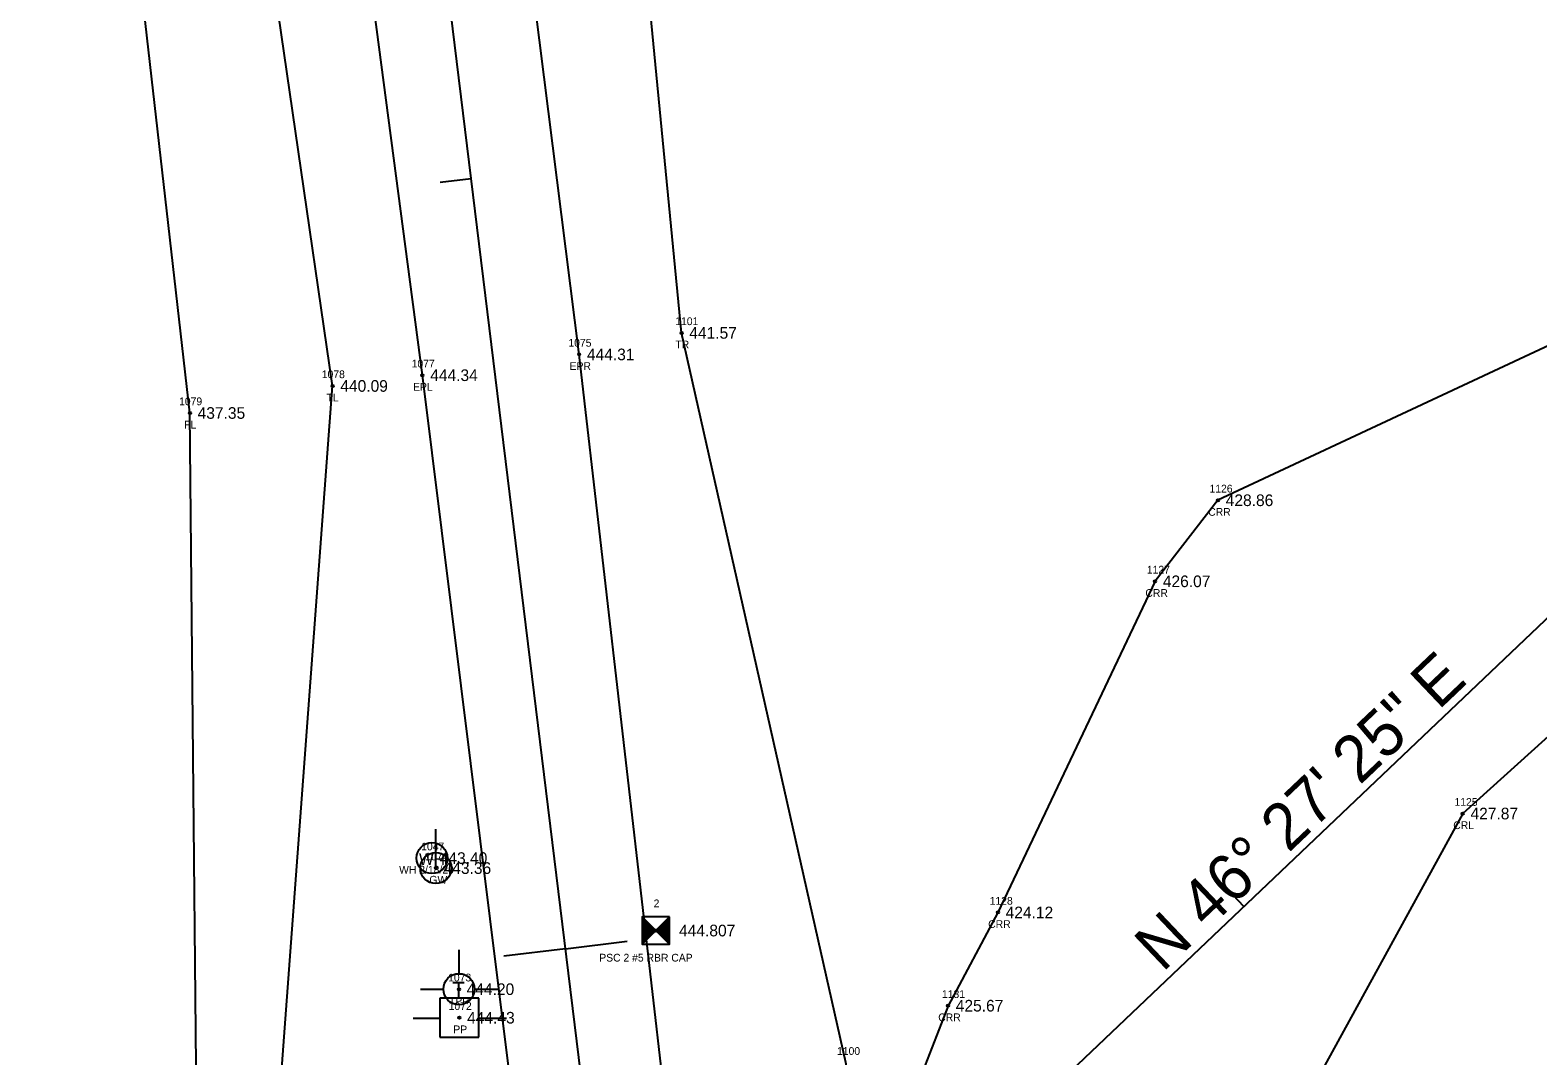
# Model space of a CAD drawing. Extents: x 1858454 to 1858924, y 1147053 to 1148170.
# Drawn here: x 1858606.4 to 1858800.8, y 1147671.2 to 1147803.4 of the extents above; entities that cross this region are included whole.
import ezdxf

# ---------------------------------------------------------------- set-up
doc = ezdxf.new("R2010")
doc.units = 0
for name, color, linetype in [('RD_EX_Fence_Other', 7, 'Continuous'), ('RD_EX_Fence_Other_txCode', 7, 'Continuous'), ('RD_EX_H2O', 7, 'Continuous'), ('RD_EX_H2O_txCode', 7, 'Continuous'), ('RD_EX_Road', 7, 'Continuous'), ('RD_EX_Road_txCode', 7, 'Continuous'), ('RD_EX_TX_Fence_Other_ELEV', 7, 'Continuous'), ('RD_EX_TX_H2O_ELEV', 7, 'Continuous'), ('RD_EX_TX_Road_ELEV', 7, 'Continuous'), ('RD_EX_TX_UT_ELEV', 7, 'Continuous'), ('RD_EX_TX_VEG_ELEV', 7, 'Continuous'), ('RD_EX_UT', 7, 'Continuous'), ('RD_EX_UT_txCode', 7, 'Continuous'), ('RD_EX_VEG', 7, 'Continuous'), ('RD_EX_VEG_txCode', 7, 'Continuous'), ('RD_HC_Cl', 7, 'Continuous'), ('RD_HC_Data', 7, 'Continuous'), ('RD_HC_Data_Tic', 7, 'Continuous'), ('RD_HC_Survey', 7, 'Continuous'), ('RD_HC_Survey_ELEV', 7, 'Continuous'), ('RD_HC_txCode', 7, 'Continuous'), ('RD_SMD_Locator', 7, 'Continuous')]:
    doc.layers.add(name, color=color, linetype=linetype)

msp = doc.modelspace()

# ---------------------------------------------------------------- linework, layer by layer
at = {"layer": 'RD_EX_Fence_Other'}
msp.add_lwpolyline([(1858628.27, 1147625.58), (1858627.01, 1147754.05), (1858615.95, 1147851.08), (1858606.98, 1147957.76), (1858595.17, 1148052.68), (1858581.78, 1148154.12)], dxfattribs=at)
at = {"layer": 'RD_EX_H2O'}
for points in [[(1858879.83, 1148102.54), (1858871.42, 1148034.27), (1858866.93, 1147971.73), (1858863.21, 1147909.44), (1858860.9, 1147860.04), (1858873.82, 1147825.54), (1858891.79, 1147781.55), (1858894.95, 1147773.07), (1858887.01, 1147735.25), (1858825.08, 1147733.03), (1858791.14, 1147702.41), (1858765.02, 1147654.77), (1858740.99, 1147628.76), (1858706.35, 1147596.83), (1858671.87, 1147580.02), (1858637.61, 1147560.56), (1858613.46, 1147539.88), (1858609.2, 1147499), (1858608.26, 1147474.71), (1858583.43, 1147442.99), (1858542.68, 1147417.32), (1858497.34, 1147430.55)], [(1858842, 1147848.22), (1858847.52, 1147794.04), (1858841.16, 1147786.48), (1858816.23, 1147769.28), (1858759.58, 1147742.8), (1858751.47, 1147732.35), (1858731.2, 1147689.66), (1858724.77, 1147677.64), (1858718.76, 1147662.14), (1858713.87, 1147646.5), (1858696.23, 1147629.99), (1858681.73, 1147631.9), (1858663.61, 1147613.98), (1858627.73, 1147602.37), (1858587.46, 1147561.81), (1858570.79, 1147529.07), (1858577.35, 1147512.16), (1858564.18, 1147528.65), (1858536.5, 1147564.8), (1858503.8, 1147609.24)]]:
    msp.add_lwpolyline(points, dxfattribs=at)
for radius in [2, 0.005]:
    msp.add_circle((1858658.23, 1147696.67), radius, dxfattribs=at)
at = {"layer": 'RD_EX_Road'}
for points in [[(1858679.02, 1147660.19), (1858688.73, 1147661.54), (1858677.21, 1147761.6), (1858664.75, 1147860.38), (1858652.33, 1147959.9), (1858640.18, 1148058.71), (1858627.63, 1148158.94)], [(1858679.02, 1147660.19), (1858669.49, 1147658.82), (1858657, 1147758.92), (1858643.96, 1147857.84), (1858631.87, 1147958), (1858619.69, 1148055.49), (1858606.59, 1148156.75)]]:
    msp.add_lwpolyline(points, dxfattribs=at)
at = {"layer": 'RD_EX_UT'}
for p, q in [((1858658.73, 1147695.38), (1858658.73, 1147700.38)), ((1858661.7, 1147684.84), (1858661.7, 1147681.77)), ((1858656.76, 1147679.78), (1858659.7, 1147679.78)), ((1858664.25, 1147678.6), (1858659.25, 1147678.6)), ((1858659.25, 1147678.6), (1858659.25, 1147673.6)), ((1858663.7, 1147679.78), (1858666.76, 1147679.78)), ((1858664.25, 1147673.6), (1858664.25, 1147678.6)), ((1858655.82, 1147676.04), (1858659.29, 1147676.04)), ((1858664.18, 1147676.04), (1858667.82, 1147676.04)), ((1858659.25, 1147673.6), (1858664.25, 1147673.6))]:
    msp.add_line(p, q, dxfattribs=at)
for centre in [(1858658.73, 1147695.38), (1858661.7, 1147679.77)]:
    msp.add_circle(centre, 2, dxfattribs=at)
at = {"layer": 'RD_EX_VEG'}
for points in [[(1858786.58, 1147073.62), (1858775.98, 1147174.64), (1858762.89, 1147274.03), (1858752.24, 1147373.24), (1858736.96, 1147479.89), (1858729.06, 1147571.9), (1858711.6, 1147670.3), (1858690.41, 1147764.38), (1858680.89, 1147862.43), (1858668.42, 1147961.01), (1858651.26, 1148061.01), (1858641.53, 1148160.37)], [(1858726.29, 1147071.02), (1858708.41, 1147166.41), (1858698.92, 1147264.27), (1858694.52, 1147368.74), (1858682.22, 1147467.57), (1858636.43, 1147636.58), (1858645.41, 1147757.54), (1858631.11, 1147856.08), (1858618.46, 1147956.68), (1858606.82, 1148055.62), (1858592.91, 1148154.69)]]:
    msp.add_lwpolyline(points, dxfattribs=at)
at = {"layer": 'RD_HC_Cl'}
for p, q in [((1858750.25, 1147074.55), (1858617.68, 1148156.23)), ((1858683.96, 1147615.39), (1858865, 1147787.44))]:
    msp.add_line(p, q, dxfattribs=at)
at = {"layer": 'RD_HC_Data_Tic'}
for p, q in [((1858663.27, 1147784.24), (1858659.3, 1147783.76)), ((1858762.93, 1147690.43), (1858760.17, 1147693.33)), ((1858675.44, 1147684.99), (1858667.49, 1147684.01)), ((1858675.44, 1147684.99), (1858683.38, 1147685.96))]:
    msp.add_line(p, q, dxfattribs=at)
at = {"layer": 'RD_HC_Survey'}
for p, q in [((1858685.34, 1147689.08), (1858688.84, 1147685.58)), ((1858688.84, 1147689.08), (1858685.34, 1147685.58)), ((1858685.37, 1147689.06), (1858685.37, 1147685.61)), ((1858685.39, 1147689.03), (1858685.39, 1147685.63)), ((1858685.42, 1147689.01), (1858685.42, 1147685.65)), ((1858685.44, 1147688.98), (1858685.44, 1147685.68)), ((1858685.47, 1147688.96), (1858685.47, 1147685.7)), ((1858685.49, 1147688.93), (1858685.49, 1147685.73)), ((1858685.52, 1147688.91), (1858685.52, 1147685.75)), ((1858685.54, 1147688.88), (1858685.54, 1147685.78)), ((1858685.56, 1147688.86), (1858685.56, 1147685.8)), ((1858685.59, 1147688.83), (1858685.59, 1147685.83)), ((1858685.61, 1147688.81), (1858685.61, 1147685.85)), ((1858685.64, 1147688.78), (1858685.64, 1147685.88)), ((1858685.66, 1147688.76), (1858685.66, 1147685.9)), ((1858685.69, 1147688.73), (1858685.69, 1147685.93)), ((1858685.71, 1147688.71), (1858685.71, 1147685.95)), ((1858685.74, 1147688.68), (1858685.74, 1147685.98)), ((1858685.76, 1147688.66), (1858685.76, 1147686)), ((1858685.79, 1147688.63), (1858685.79, 1147686.03)), ((1858685.81, 1147688.61), (1858685.81, 1147686.05)), ((1858685.84, 1147688.59), (1858685.84, 1147686.08)), ((1858685.86, 1147688.56), (1858685.86, 1147686.1)), ((1858685.89, 1147688.54), (1858685.89, 1147686.12)), ((1858685.91, 1147688.51), (1858685.91, 1147686.15)), ((1858685.94, 1147688.49), (1858685.94, 1147686.17)), ((1858685.96, 1147688.46), (1858685.96, 1147686.2)), ((1858685.99, 1147688.44), (1858685.99, 1147686.22)), ((1858686.01, 1147688.41), (1858686.01, 1147686.25)), ((1858686.03, 1147688.39), (1858686.03, 1147686.27)), ((1858686.06, 1147688.36), (1858686.06, 1147686.3)), ((1858686.08, 1147688.34), (1858686.08, 1147686.32)), ((1858686.11, 1147688.31), (1858686.11, 1147686.35)), ((1858686.13, 1147688.29), (1858686.13, 1147686.37)), ((1858686.16, 1147688.26), (1858686.16, 1147686.4)), ((1858686.18, 1147688.24), (1858686.18, 1147686.42)), ((1858686.21, 1147688.21), (1858686.21, 1147686.45)), ((1858686.23, 1147688.19), (1858686.23, 1147686.47)), ((1858686.26, 1147688.16), (1858686.26, 1147686.5)), ((1858686.28, 1147688.14), (1858686.28, 1147686.52)), ((1858686.31, 1147688.12), (1858686.31, 1147686.55)), ((1858686.33, 1147688.09), (1858686.33, 1147686.57)), ((1858686.36, 1147688.07), (1858686.36, 1147686.6)), ((1858686.38, 1147688.04), (1858686.38, 1147686.62)), ((1858686.41, 1147688.02), (1858686.41, 1147686.64)), ((1858686.43, 1147687.99), (1858686.43, 1147686.67)), ((1858686.46, 1147687.97), (1858686.46, 1147686.69)), ((1858686.48, 1147687.94), (1858686.48, 1147686.72)), ((1858687.7, 1147687.94), (1858687.7, 1147686.72)), ((1858687.73, 1147687.97), (1858687.73, 1147686.69)), ((1858687.75, 1147687.99), (1858687.75, 1147686.67)), ((1858687.78, 1147688.02), (1858687.78, 1147686.64)), ((1858687.8, 1147688.04), (1858687.8, 1147686.62)), ((1858687.83, 1147688.07), (1858687.83, 1147686.6)), ((1858687.85, 1147688.09), (1858687.85, 1147686.57)), ((1858687.88, 1147688.12), (1858687.88, 1147686.55)), ((1858687.9, 1147688.14), (1858687.9, 1147686.52)), ((1858687.93, 1147688.16), (1858687.93, 1147686.5)), ((1858687.95, 1147688.19), (1858687.95, 1147686.47)), ((1858687.98, 1147688.21), (1858687.98, 1147686.45)), ((1858688, 1147688.24), (1858688, 1147686.42)), ((1858688.03, 1147688.26), (1858688.03, 1147686.4)), ((1858688.05, 1147688.29), (1858688.05, 1147686.37)), ((1858688.07, 1147688.31), (1858688.07, 1147686.35)), ((1858688.1, 1147688.34), (1858688.1, 1147686.32)), ((1858688.12, 1147688.36), (1858688.12, 1147686.3)), ((1858688.15, 1147688.39), (1858688.15, 1147686.27)), ((1858688.17, 1147688.41), (1858688.17, 1147686.25)), ((1858688.2, 1147688.44), (1858688.2, 1147686.22)), ((1858688.22, 1147688.46), (1858688.22, 1147686.2)), ((1858688.25, 1147688.49), (1858688.25, 1147686.17)), ((1858688.27, 1147688.51), (1858688.27, 1147686.15)), ((1858688.3, 1147688.54), (1858688.3, 1147686.12)), ((1858688.32, 1147688.56), (1858688.32, 1147686.1)), ((1858688.35, 1147688.59), (1858688.35, 1147686.08)), ((1858688.37, 1147688.61), (1858688.37, 1147686.05)), ((1858688.4, 1147688.63), (1858688.4, 1147686.03)), ((1858688.42, 1147688.66), (1858688.42, 1147686)), ((1858688.45, 1147688.68), (1858688.45, 1147685.98)), ((1858688.47, 1147688.71), (1858688.47, 1147685.95)), ((1858688.5, 1147688.73), (1858688.5, 1147685.93)), ((1858688.52, 1147688.76), (1858688.52, 1147685.9)), ((1858688.54, 1147688.78), (1858688.54, 1147685.88)), ((1858688.57, 1147688.81), (1858688.57, 1147685.85)), ((1858688.59, 1147688.83), (1858688.59, 1147685.83)), ((1858688.62, 1147688.86), (1858688.62, 1147685.8)), ((1858688.64, 1147688.88), (1858688.64, 1147685.78)), ((1858688.67, 1147688.91), (1858688.67, 1147685.75)), ((1858688.69, 1147688.93), (1858688.69, 1147685.73)), ((1858688.72, 1147688.96), (1858688.72, 1147685.7)), ((1858688.74, 1147688.98), (1858688.74, 1147685.68)), ((1858688.77, 1147689.01), (1858688.77, 1147685.65)), ((1858688.79, 1147689.03), (1858688.79, 1147685.63)), ((1858688.82, 1147689.06), (1858688.82, 1147685.61)), ((1858686.5, 1147687.92), (1858686.5, 1147686.74)), ((1858686.53, 1147687.89), (1858686.53, 1147686.77)), ((1858686.55, 1147687.87), (1858686.55, 1147686.79)), ((1858686.58, 1147687.84), (1858686.58, 1147686.82)), ((1858686.6, 1147687.82), (1858686.6, 1147686.84)), ((1858686.63, 1147687.79), (1858686.63, 1147686.87)), ((1858686.65, 1147687.77), (1858686.65, 1147686.89)), ((1858686.68, 1147687.74), (1858686.68, 1147686.92)), ((1858686.7, 1147687.72), (1858686.7, 1147686.94)), ((1858686.73, 1147687.69), (1858686.73, 1147686.97)), ((1858686.75, 1147687.67), (1858686.75, 1147686.99)), ((1858686.78, 1147687.64), (1858686.78, 1147687.02)), ((1858686.8, 1147687.62), (1858686.8, 1147687.04)), ((1858686.83, 1147687.6), (1858686.83, 1147687.07)), ((1858686.85, 1147687.57), (1858686.85, 1147687.09)), ((1858686.88, 1147687.55), (1858686.88, 1147687.11)), ((1858686.9, 1147687.52), (1858686.9, 1147687.14)), ((1858686.93, 1147687.5), (1858686.93, 1147687.16)), ((1858686.95, 1147687.47), (1858686.95, 1147687.19)), ((1858686.98, 1147687.45), (1858686.98, 1147687.21)), ((1858687, 1147687.42), (1858687, 1147687.24)), ((1858687.02, 1147687.4), (1858687.02, 1147687.26)), ((1858687.05, 1147687.37), (1858687.05, 1147687.29)), ((1858687.07, 1147687.35), (1858687.07, 1147687.31)), ((1858687.11, 1147687.35), (1858687.11, 1147687.31)), ((1858687.13, 1147687.37), (1858687.13, 1147687.29)), ((1858687.16, 1147687.4), (1858687.16, 1147687.26)), ((1858687.18, 1147687.42), (1858687.18, 1147687.24)), ((1858687.21, 1147687.45), (1858687.21, 1147687.21)), ((1858687.23, 1147687.47), (1858687.23, 1147687.19)), ((1858687.26, 1147687.5), (1858687.26, 1147687.16)), ((1858687.28, 1147687.52), (1858687.28, 1147687.14)), ((1858687.31, 1147687.55), (1858687.31, 1147687.11)), ((1858687.33, 1147687.57), (1858687.33, 1147687.09)), ((1858687.36, 1147687.6), (1858687.36, 1147687.07)), ((1858687.38, 1147687.62), (1858687.38, 1147687.04)), ((1858687.41, 1147687.64), (1858687.41, 1147687.02)), ((1858687.43, 1147687.67), (1858687.43, 1147686.99)), ((1858687.46, 1147687.69), (1858687.46, 1147686.97)), ((1858687.48, 1147687.72), (1858687.48, 1147686.94)), ((1858687.51, 1147687.74), (1858687.51, 1147686.92)), ((1858687.53, 1147687.77), (1858687.53, 1147686.89)), ((1858687.55, 1147687.79), (1858687.55, 1147686.87)), ((1858687.58, 1147687.82), (1858687.58, 1147686.84)), ((1858687.6, 1147687.84), (1858687.6, 1147686.82)), ((1858687.63, 1147687.87), (1858687.63, 1147686.79)), ((1858687.65, 1147687.89), (1858687.65, 1147686.77)), ((1858687.68, 1147687.92), (1858687.68, 1147686.74))]:
    msp.add_line(p, q, dxfattribs=at)
msp.add_lwpolyline([(1858688.84, 1147689.08), (1858685.34, 1147689.08), (1858685.34, 1147685.58), (1858688.84, 1147685.58)], close=True, dxfattribs=at)
at = {"layer": 'RD_SMD_Locator'}
for centre in [(1858690.41, 1147764.38), (1858677.21, 1147761.6), (1858657, 1147758.92), (1858645.41, 1147757.54), (1858627.01, 1147754.05), (1858759.58, 1147742.8), (1858751.47, 1147732.35), (1858791.14, 1147702.41), (1858658.73, 1147695.38), (1858731.2, 1147689.66), (1858687.09, 1147687.33), (1858661.7, 1147679.77), (1858724.77, 1147677.64), (1858661.76, 1147676.09)]:
    msp.add_circle(centre, 0.15, dxfattribs=at)

# ---------------------------------------------------------------- texts
at = {"layer": 'RD_EX_Fence_Other_txCode'}
for s, p in [('1079', (1858625.62, 1147755.05)), ('FL', (1858626.27, 1147752.05))]:
    msp.add_text(s, height=1, dxfattribs=at).set_placement(p)
at = {"layer": 'RD_EX_H2O'}
msp.add_text('WH', height=1.5, dxfattribs=at).set_placement((1858656.56, 1147695.79))
at = {"layer": 'RD_EX_H2O_txCode'}
for s, p in [('1126', (1858758.49, 1147743.8)), ('CRR', (1858758.32, 1147740.8)), ('1127', (1858750.41, 1147733.35)), ('CRR', (1858750.22, 1147730.35)), ('1125', (1858790.08, 1147703.41)), ('CRL', (1858789.92, 1147700.41)), ('1047', (1858656.84, 1147697.67)), ('WH 2/18/20', (1858653.99, 1147694.67)), ('1128', (1858730.14, 1147690.66)), ('CRR', (1858729.95, 1147687.66)), ('1131', (1858723.99, 1147678.64)), ('CRR', (1858723.51, 1147675.64))]:
    msp.add_text(s, height=1, dxfattribs=at).set_placement(p)
at = {"layer": 'RD_EX_Road_txCode'}
for s, p in [('1075', (1858675.82, 1147762.6)), ('1077', (1858655.61, 1147759.92)), ('EPR', (1858675.98, 1147759.6)), ('EPL', (1858655.79, 1147756.92))]:
    msp.add_text(s, height=1, dxfattribs=at).set_placement(p)
at = {"layer": 'RD_EX_TX_Fence_Other_ELEV'}
msp.add_text('437.35', height=1.5, dxfattribs=at).set_placement((1858628.01, 1147753.3))
at = {"layer": 'RD_EX_TX_H2O_ELEV'}
for s, p in [('428.86', (1858760.58, 1147742.05)), ('426.07', (1858752.47, 1147731.6)), ('427.87', (1858792.14, 1147701.66)), ('443.40', (1858659.23, 1147695.92)), ('424.12', (1858732.2, 1147688.91)), ('425.67', (1858725.77, 1147676.89))]:
    msp.add_text(s, height=1.5, dxfattribs=at).set_placement(p)
at = {"layer": 'RD_EX_TX_Road_ELEV'}
for s, p in [('444.31', (1858678.21, 1147760.85)), ('444.34', (1858658, 1147758.17))]:
    msp.add_text(s, height=1.5, dxfattribs=at).set_placement(p)
at = {"layer": 'RD_EX_TX_UT_ELEV'}
for s, p in [('443.36', (1858659.73, 1147694.63)), ('444.20', (1858662.7, 1147679.02))]:
    msp.add_text(s, height=1.5, dxfattribs=at).set_placement(p)
at = {"layer": 'RD_EX_TX_VEG_ELEV'}
for s, p in [('441.57', (1858691.41, 1147763.63)), ('440.09', (1858646.41, 1147756.79))]:
    msp.add_text(s, height=1.5, dxfattribs=at).set_placement(p)
at = {"layer": 'RD_EX_UT'}
msp.add_text('T', height=2, dxfattribs=at).set_placement((1858660.85, 1147678.72))
at = {"layer": 'RD_EX_UT_txCode'}
for s, p in [('1074', (1858657.35, 1147696.38)), ('GW', (1858657.89, 1147693.38)), ('1073', (1858660.31, 1147680.77)), ('TPP', (1858660.43, 1147677.77)), ('1072', (1858660.38, 1147677.09)), ('PP', (1858660.98, 1147674.09))]:
    msp.add_text(s, height=1, dxfattribs=at).set_placement(p)
at = {"layer": 'RD_EX_VEG_txCode'}
for s, p in [('1101', (1858689.6, 1147765.38)), ('TR', (1858689.62, 1147762.38)), ('1078', (1858644.02, 1147758.54)), ('TL', (1858644.64, 1147755.54)), ('1100', (1858710.46, 1147671.3))]:
    msp.add_text(s, height=1, dxfattribs=at).set_placement(p)
at = {"layer": 'RD_HC_Data'}
msp.add_text('N 46%%d 27\' 25" E', height=6, rotation=43.5432, dxfattribs=at).set_placement((1858752.44, 1147681.85))
at = {"layer": 'RD_HC_Survey_ELEV'}
for s, p in [('444.807', (1858690.09, 1147686.58)), ('444.43', (1858662.76, 1147675.34))]:
    msp.add_text(s, height=1.5, dxfattribs=at).set_placement(p)
at = {"layer": 'RD_HC_txCode'}
for s, p in [('2', (1858686.81, 1147690.33)), ('PSC 2 #5 RBR CAP', (1858679.8, 1147683.33))]:
    msp.add_text(s, height=1, dxfattribs=at).set_placement(p)

doc.saveas('drawing.dxf')
